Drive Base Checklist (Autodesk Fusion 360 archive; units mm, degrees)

design "Drive Base Checklist" references "Spacer 0.280in x 0.382in", "Bearing R6ZZ", "Front Bumper Bracket", "Half Pulley 42t", "Spacer 0.850in x 0.380in", "Bearing FR6ZZ", "Bottom Battery Plate", "Side Mount Bumper Bracket", "Bearing FR8ZZ Hex", "6in HiGrip Wheel", "Nylock Nut 10-32 (optional)", "C Plate", "500 churro", "Tough Box large cluster gear", "AM14U5 Outside Plate", "Bearing FR8ZZ", "CIM gear 14 tooth", "AM14U5 End Plate", "Vertical Battery Mount Strap Clamp", "AM14U5 Inside Plate"
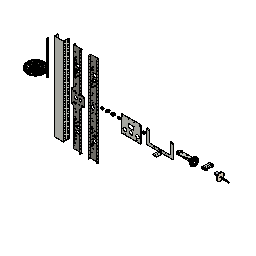
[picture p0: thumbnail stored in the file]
component_insert "Component Insert1"
component_insert "Component Insert2"
component_insert "Component Insert3"
component_insert "Component Insert4"
component_insert "Component Insert5"
component_insert "Component Insert6"
component_insert "Component Insert7"
component_insert "Component Insert8"
component_insert "Component Insert9"
component_insert "Component Insert10"
component_insert "Component Insert11"
component_insert "Component Insert12"
component_insert "Component Insert13"
component_insert "Component Insert14"
component_insert "Component Insert15"
component_insert "Component Insert16"
component_insert "Component Insert17"
component_insert "Component Insert18"
component_insert "Component Insert19"
component_insert "Component Insert20"

design "Front Bumper Bracket"
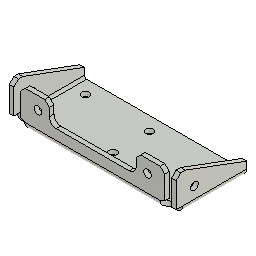
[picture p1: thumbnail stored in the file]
base_feature "Base Feature"

design "500 churro"
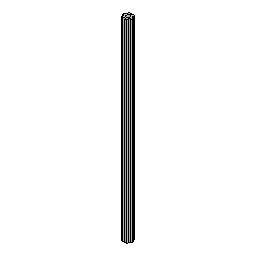
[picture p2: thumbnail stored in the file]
base_feature "Base Feature"

design "AM14U5 Inside Plate"
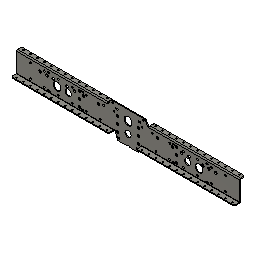
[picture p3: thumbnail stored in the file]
base_feature "Base Feature"

design "Half Pulley 42t"
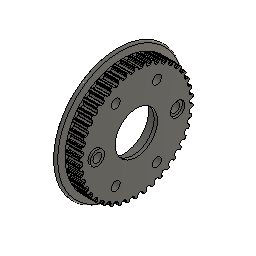
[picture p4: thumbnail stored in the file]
base_feature "Base Feature"

design "AM14U5 Outside Plate"
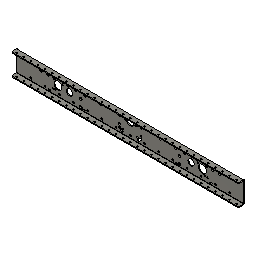
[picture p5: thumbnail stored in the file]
base_feature "Base Feature"

design "Tough Box large cluster gear"
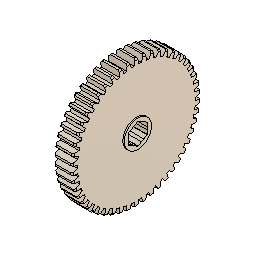
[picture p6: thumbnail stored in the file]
base_feature "Base Feature"

design "Spacer 0.280in x 0.382in"
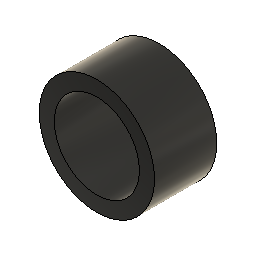
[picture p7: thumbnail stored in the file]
base_feature "Base Feature"

design "Bearing FR8ZZ"
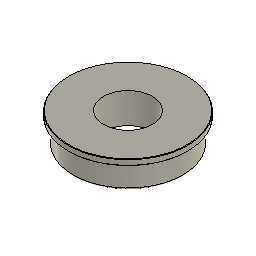
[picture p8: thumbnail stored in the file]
base_feature "Base Feature"

design "Bottom Battery Plate"
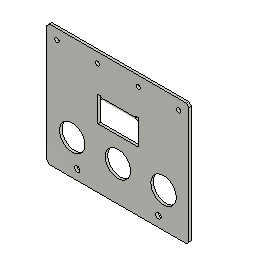
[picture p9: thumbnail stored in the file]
base_feature "Base Feature"

design "Bearing FR6ZZ"
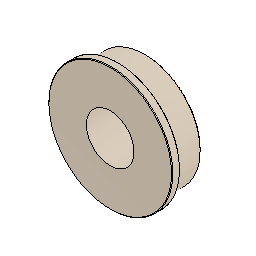
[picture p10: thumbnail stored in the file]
base_feature "Base Feature"

design "CIM gear 14 tooth"
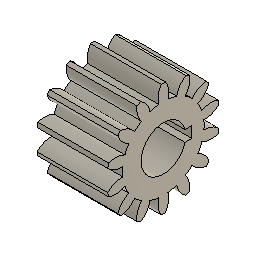
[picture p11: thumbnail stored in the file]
base_feature "Base Feature"

design "6in HiGrip Wheel"
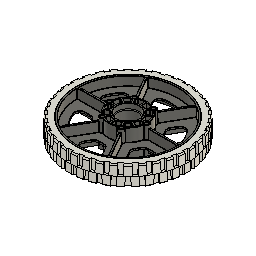
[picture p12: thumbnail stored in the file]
base_feature "Base Feature1"
base_feature "Base Feature1"
as_built_joint "As-built1"
joint "Assemble1" alignAngle 180 alignOffsetX 0 alignOffsetY 0 alignOffsetZ 0
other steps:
create_component "CreateComponent1"
create_component "CreateComponent2"
joint_origin "JointOrigin1"
joint_origin "JointOrigin1"

design "Bearing R6ZZ"
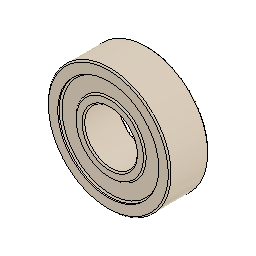
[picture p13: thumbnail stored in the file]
base_feature "Base Feature"

design "Vertical Battery Mount Strap Clamp"
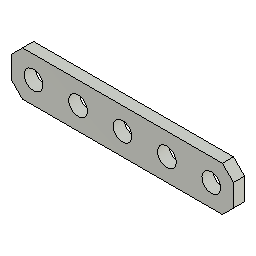
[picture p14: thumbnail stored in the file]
base_feature "Base Feature"

design "Spacer 0.850in x 0.380in"
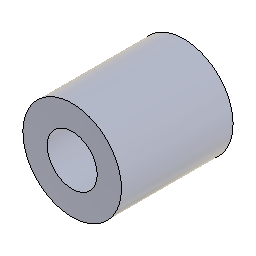
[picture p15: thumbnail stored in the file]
base_feature "Base Feature"

design "Bearing FR8ZZ Hex"
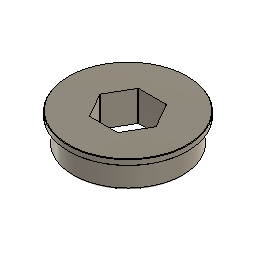
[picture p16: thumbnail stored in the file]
base_feature "Base Feature"

design "AM14U5 End Plate"
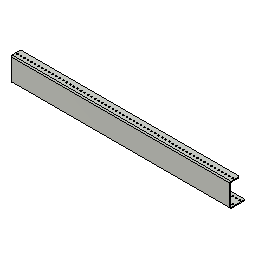
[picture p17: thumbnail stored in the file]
base_feature "Base Feature"

design "Nylock Nut 10-32 (optional)"
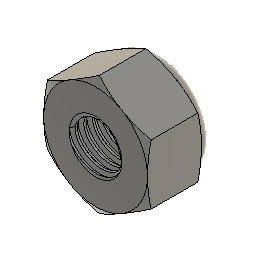
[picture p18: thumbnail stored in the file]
base_feature "Base Feature"

design "Side Mount Bumper Bracket"
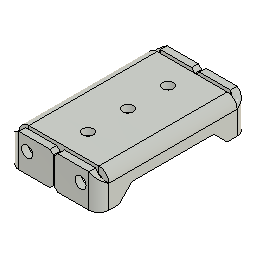
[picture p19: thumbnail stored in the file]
base_feature "Base Feature"

design "C Plate"
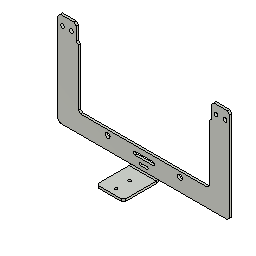
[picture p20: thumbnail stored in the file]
base_feature "Base Feature"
